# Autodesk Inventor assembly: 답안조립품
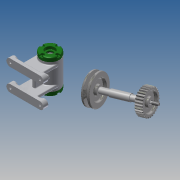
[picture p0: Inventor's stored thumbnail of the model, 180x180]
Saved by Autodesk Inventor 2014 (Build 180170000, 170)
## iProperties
Created: 2015-11
Part Number: 답안조립품
Document SubType Name: Assembly
Designer: 12
Author: 12
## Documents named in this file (8)
- C:\Users\12\Desktop\451110V1046\답안조립품.iam
- C:\Users\12\Desktop\451110V1046\본체.ipt
- C:\Users\12\Desktop\451110V1046\V벨트풀리.ipt
- C:\Users\12\Desktop\451110V1046\축.ipt
- C:\Users\12\Desktop\451110V1046\스퍼기어.ipt
- C:\Users\12\Desktop\451110V1046\키 3 x 3 x 12.ipt
- C:\Users\12\Desktop\451110V1046\베어링 15 x 32 x 9.ipt
- C:\Users\12\Desktop\451110V1046\커버.ipt
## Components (3 placed, 2 different names)
1. V벨트풀리:1
2. KS B 2023 6002 - 15 x 32 x 9:1
3. KS B 2023 6002 - 15 x 32 x 9:2
